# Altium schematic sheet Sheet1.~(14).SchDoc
size A4; SheetNumber: 1; SheetTotal: 1
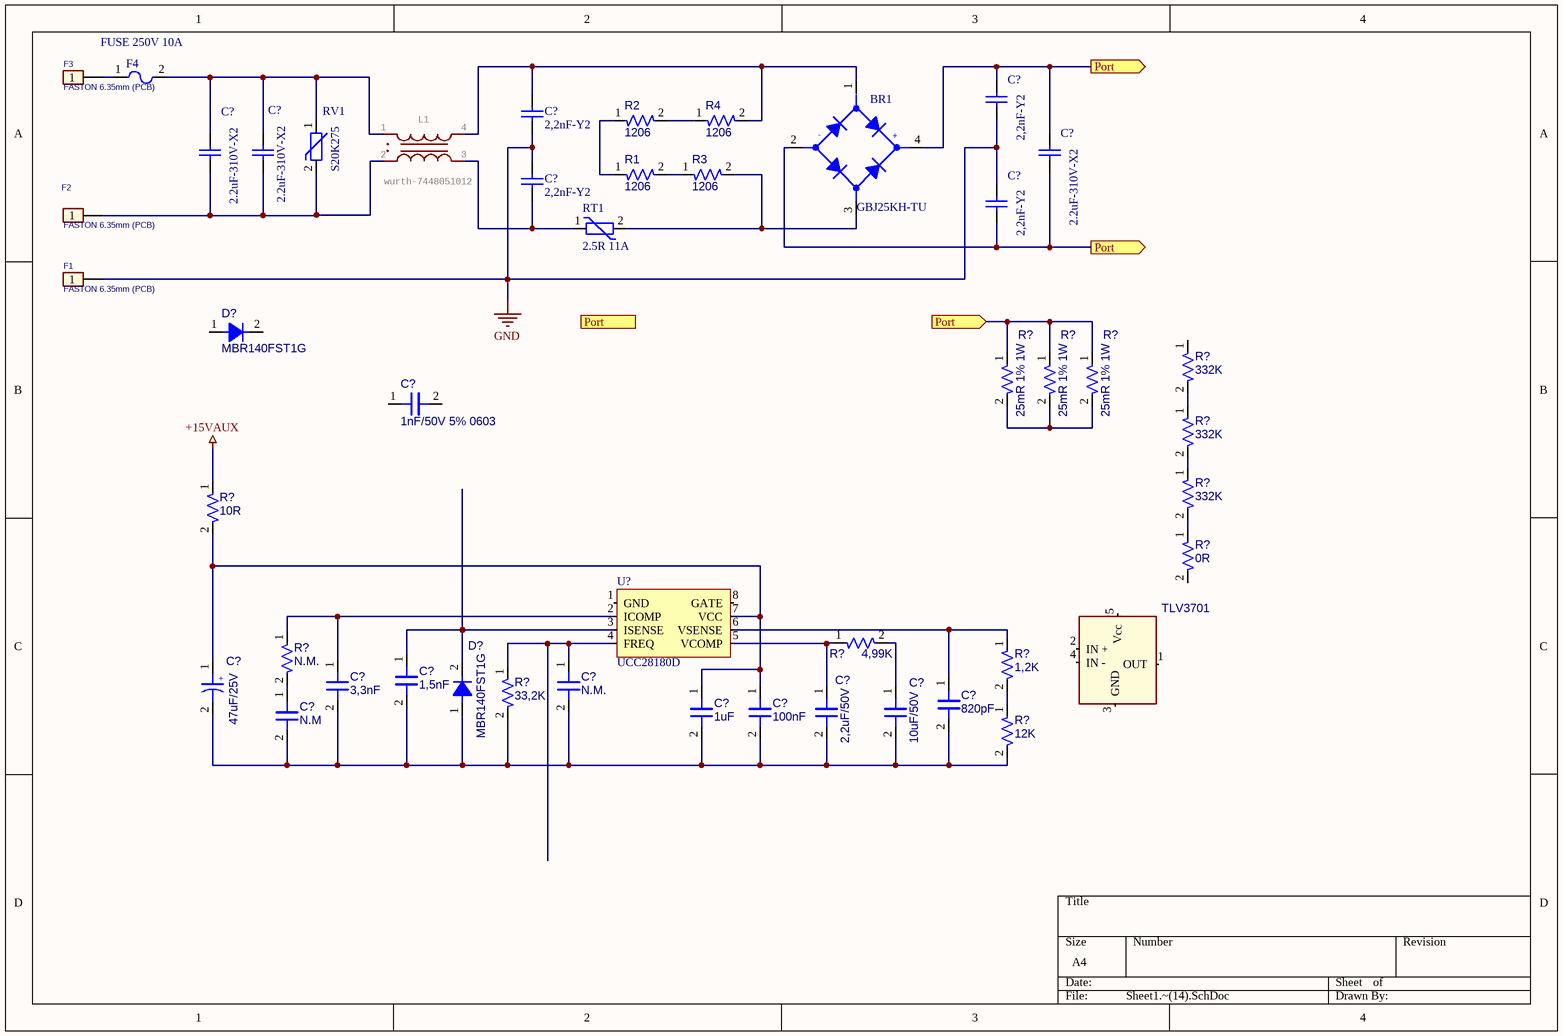
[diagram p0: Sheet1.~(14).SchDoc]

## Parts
(Parts that share a designator on the sheet are numbered #1, #2 ... from top to bottom, then left to right.)
BR1  GBJ25KH-TU
C?#1  2,2nF-Y2
C?#2  2,2nF-Y2
C?#3  2.2uF-310V-X2
C?#4  2.2uF-310V-X2
C?#5  2.2uF-310V-X2
C?#6  2,2nF-Y2
C?#7  2,2nF-Y2
C?#8  1nF/50V 5% 0603  [0603N_CAP]
C?#9  1,5nF  [0603N_CAP]
C?#10  47uF/25V  [ELETTROLITICO_CASE_D]
C?#11  3,3nF  [0603N_CAP]
C?#12  N.M.  [0603N_CAP]
C?#13  820pF  [0603N_CAP]
C?#14  N.M  [0603N_CAP]
C?#15  1uF  [0603N_CAP]
C?#16  100nF  [0603N_CAP]
C?#17  2,2uF/50V  [1206_UP_CAP]
C?#18  10uF/50V  [1206_UP_CAP]
D?#1  MBR140FST1G
D?#2  MBR140FST1G
F1  FASTON 6.35mm (PCB)  [FASTON_M_PCB_6.35x0.81]
F2  FASTON 6.35mm (PCB)  [FASTON_M_PCB_6.35x0.81]
F3  FASTON 6.35mm (PCB)  [FASTON_M_PCB_6.35x0.81]
F4  FUSE 250V 10A
L1  wurth-7448051012  [WE-CMBNC_XL_7448051012]
R1  1206  [1206_UP_RES]
R2  1206  [1206_UP_RES]
R3  1206  [1206_UP_RES]
R4  1206  [1206_UP_RES]
R?#1  332K  [1206_UP_RES]
R?#2  25mR 1% 1W  [2512_up]
R?#3  25mR 1% 1W  [2512_up]
R?#4  25mR 1% 1W  [2512_up]
R?#5  332K  [1206_UP_RES]
R?#6  332K  [1206_UP_RES]
R?#7  10R  [1206_UP_RES]
R?#8  0R  [1206_UP_RES]
R?#9  N.M.  [0603N_RES]
R?#10  1,2K  [1206_UP_RES]
R?#11  4,99K  [0603N_RES]
R?#12  33,2K  [0603N_RES]
R?#13  12K  [1206_UP_RES]
RT1  2.5R 11A
RV1  S20K275
TLV3701  TLV3701 SOT23-5L  [SOT-23 5PIN]  (value not drawn)
U?  UCC28180D  [SO8]

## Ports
Port (in), Port (out)

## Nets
+15VAUX: R?#7.1
GND: C?#1.1 C?#2.1 C?#6.2 C?#7.2 F1.1
Port: BR1.2(-DC) BR1.4(+DC) C?#1.2 C?#5.1 C?#5.2 C?#7.1 R?#2.1 R?#3.1 R?#4.1 ; port Port
NetBR1_1: BR1.1(AC1) C?#2.2 L1.4 R4.2
NetBR1_3: BR1.3(AC2) R3.2 RT1.2
NetC?#3_1: C?#3.1 C?#4.1 F4.2 L1.1 RV1.1
NetC?#3_2: C?#3.2 C?#4.2 F2.1 L1.2 RV1.2
NetC?#6_1: C?#6.1 L1.3 RT1.1
NetC?#9_1: C?#9.1 D?#2.2 U?.3(ISENSE)
NetC?#9_2: C?#9.2 C?#10.2 C?#11.2 C?#12.2 C?#13.2 C?#14.2 C?#15.2 C?#16.2 C?#17.2 C?#18.2 D?#2.1 R?#12.2 R?#13.2
NetC?#10_1: C?#10.1 C?#15.1 C?#16.1 R?#7.2 U?.7(VCC)
NetC?#11_1: C?#11.1 R?#9.1 U?.2(ICOMP)
NetC?#12_1: C?#12.1 R?#12.1 U?.4(FREQ)
NetC?#13_1: C?#13.1 R?#10.1 U?.6(VSENSE)
NetC?#14_1: C?#14.1 R?#9.2
NetC?#17_1: C?#17.1 R?#11.1 U?.5(VCOMP)
NetC?#18_1: C?#18.1 R?#11.2
NetF3_1: F3.1 F4.1
NetR1_1: R1.1 R2.1
NetR1_2: R1.2 R3.1
NetR2_2: R2.2 R4.1
NetR?#1_2: R?#1.2 R?#5.1
NetR?#2_2: R?#2.2 R?#3.2 R?#4.2
NetR?#5_2: R?#5.2 R?#6.1
NetR?#6_2: R?#6.2 R?#8.1
NetR?#10_2: R?#10.2 R?#13.1

Not connected (* = marked no-connect by the designer): C?#8 1 2; D?#1 1 2; R?#1 1; R?#8 2; TLV3701 1(OUT) 2(IN_+) 3(GND) 4(IN_-) 5(Vcc); U? 1(GND) 8(GATE)

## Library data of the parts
BR1 = BRIDGE_D15XB60_15A_600V: BRIDGE DIOTEC GBJ25KH-TU 25A 800V; Costo: 0; Aggiornato: NO
C?#1 C?#2 C?#6 C?#7 = Cap: 2,2nF-Y2-300V MURATA DE6E3KJ222MA4B; Value: 2,2nF
C?#3-C?#5 = Cap: 2.2uF-310V-X2  VISHAY F339M/52231MIM2T0; Value: 2,2uF
C?#8 = CAP_NP_1nF_50V_5%_0603: Aggiornato: S; Costo: 0,01; Value: 1n; ContoLavoro: 0
C?#9 C?#11-C?#16 = CAP_NP_1nF_50V_5%_0603: 1nF/50V 5% 0603; Aggiornato: S; Costo: 0,01; Value: 1n; ContoLavoro: 0
C?#10 = CAP_P_47uF_50V_CASE_D: 47uF/50V FK SMD CASE D; Aggiornato: SI; Costo: 0,292; Value: 47u; ContoLavoro: 0
C?#17 C?#18 = CAP_NP_10uF_50V_1206_10%: CAP NP 10uF 50V 1206; Costo: 0,15; Aggiornato: S; Value: 10u; ContoLavoro: 0
D?#1 D?#2 = D_LL4148: ON SEMICUNDUCTOR, Schottky Power Rectifier, 1.0 A, 40 V, SOD-123FL; Aggiornato: SI; ContoLavoro: 0
F1-F3 = FASTON_M_PCB_6.35mm: FASTON M PCB 6.35mm; Hpcode: FASTMASCSTAMP; Costo: 0,01; Aggiornato: s; ContoLavoro: 0
F4 = FUSE_250V_6.3A_T_BEL_FUSE_0697A6300-01: PORTAFUIBILE DA C.S.  250Vac 10A 6,3x32; Aggiornato: S; ContoLavoro: 0
L1 = WE-CMBNC_XL_7448051012: GateName_1: G$1; IR: 10A; RDC: 15mOhm; VR: 250  V (AC); VT: 1500  V (AC)
R1-R4 R?#7 R?#8 R?#10 R?#13 = R_0.33_1%_1206: 1206 SMD RESISTOR; Aggiornato: s; ContoLavoro: 0
R?#1 R?#5 R?#6 = R_0.33_1%_1206: 1206 0,1% SMD RESISTOR; Aggiornato: s; ContoLavoro: 0
R?#2-R?#4 = R_0.5R_1%_2512: 25mOhm 1% 2512 1W WSL SMD RESISTOR; Costo: 0,40; Value: 0,025; Aggiornato: s; ContoLavoro: 0
R?#9 R?#11 R?#12 = R_0R_1%_0603: 0R 1% 0603 SMD RESISTOR; Costo: 0,00073; Value: 0; Aggiornato: S
RT1 = RT_2.5R_10A: NTC 2.5R 11A  TDK B57364S0259M0 21x7; Costo: 0; Aggiornato: NO
RV1 = VARISTOR: VARISTORE TDK S20K275 B72220S0271K101; Aggiornato: NO; ContoLavoro: 0
TLV3701 = TLV3701 SOT23-5L: Costo: 0; DeviceFunction: Voltage Regulator; Aggiornato: NO
U? = UCC28180D: Costo: 1,534; Aggiornato: NO; ContoLavoro: 0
